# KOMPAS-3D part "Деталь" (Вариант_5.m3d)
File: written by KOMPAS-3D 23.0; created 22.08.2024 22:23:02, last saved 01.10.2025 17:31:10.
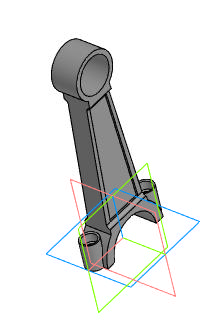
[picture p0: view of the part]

Document properties: Автор: admin; Организация: MGTU; Полное имя файла: C:\Users\ssafo\OneDrive\Desktop\ЦД_Грант\Решенные варианты\Вариант_5.m3d

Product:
- Part/product: Деталь
    Масса: 0.168946
    Форматы листов документа: A4

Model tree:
1. Эскиз:1
2. Элемент выдавливания:2
     Расстояние 1 = 7.5; Расстояние 2 = 7.5
3. Эскиз:6  (with: Элемент выдавливания:2)
4. Элемент выдавливания:8
     Расстояние 2 = 15
5. Эскиз:7  (with: Элемент выдавливания:8)
6. Элемент выдавливания:9
     Расстояние 2 = 5
7. Эскиз:8  (with: Элемент выдавливания:9)
8. Элемент выдавливания:10
     Расстояние 2 = 10
9. Зеркальный массив:3
10. Экземпляр ( 1 )
11. Экземпляр ( 2 )  (with: Элемент выдавливания:10, Элемент выдавливания:8, Элемент выдавливания:9)
12. Фаска:2  (with: Элемент выдавливания:8, Элемент выдавливания:9)
     Угол = 15; Длина 1 = 1; Длина 2 = 0.267949
13. Эскиз:9  (with: Элемент выдавливания:2)
14. Элемент выдавливания:11
     Расстояние 2 = 2
15. Эскиз:10  (with: Элемент выдавливания:11)
16. Элемент выдавливания:12
     Расстояние 2 = 1
17. Зеркальный массив:4  (with: Экземпляр ( 1 ), Экземпляр ( 2 ), Элемент выдавливания:11, Элемент выдавливания:12)
18. Скругление:1  (with: Элемент выдавливания:11)
     Радиус = 2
